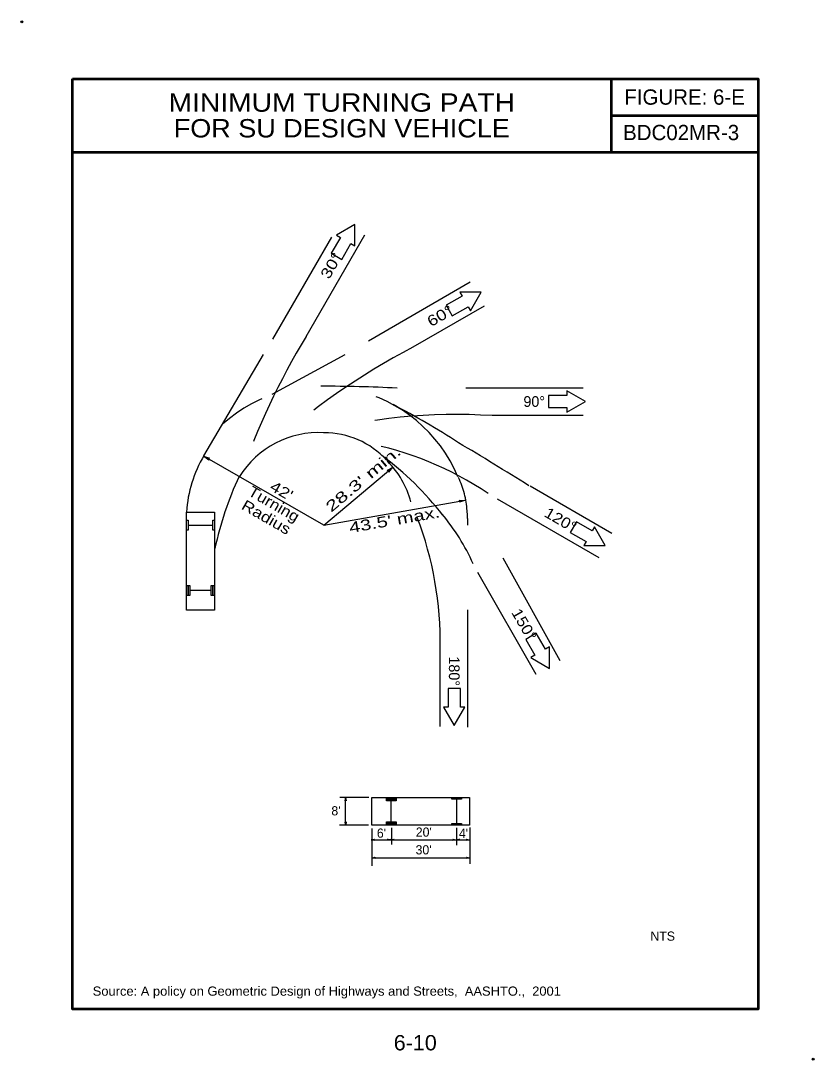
# Model space of a CAD drawing. Extents: x -3.355 to -2.68, y 3.973 to 4.857.
import ezdxf
from ezdxf.enums import TextEntityAlignment as Align

# ---------------------------------------------------------------- set-up
doc = ezdxf.new("R2010")
doc.units = 0
doc.header["$LTSCALE"] = 0.0036
doc.header["$PDMODE"] = 32
doc.header["$PDSIZE"] = 0.0018
doc.linetypes.add('LONG_DASHED', pattern=[7.5, 6, -1.5])
for name, color, linetype, lineweight in [('1', 7, 'Continuous', 25), ('2', 7, 'LONG_DASHED', 25), ('3', 7, 'Continuous', 25)]:
    doc.layers.add(name, color=color, linetype=linetype, lineweight=lineweight)

msp = doc.modelspace()

# ---------------------------------------------------------------- linework, layer by layer
at = {"layer": '1', "lineweight": 53}
for p, q in [((-2.852792, 4.80765), (-2.852792, 4.74515)), ((-2.852792, 4.7764), (-2.727792, 4.7764)), ((-3.311125, 4.74515), (-2.727792, 4.74515))]:
    msp.add_line(p, q, dxfattribs=at)
at = {"layer": '1', "linetype": 'LONG_DASHED'}
for p, q in [((-3.140583, 4.586158), (-3.081925, 4.687733)), ((-3.11225, 4.588325), (-3.0616, 4.67605)), ((-2.972667, 4.634425), (-3.078375, 4.573392)), ((-2.96095, 4.614117), (-3.021475, 4.579175)), ((-3.1993, 4.4869), (-3.140708, 4.586158)), ((-3.141308, 4.539217), (-3.079075, 4.573025)), ((-2.876517, 4.544392), (-3.034783, 4.544392)), ((-2.876517, 4.52095), (-2.954033, 4.52095)), ((-2.896075, 4.31235), (-2.983125, 4.469017)), ((-2.852075, 4.4208), (-2.921683, 4.460992)), ((-2.862925, 4.399992), (-2.957467, 4.4546)), ((-2.916583, 4.3007), (-2.970717, 4.395533))]:
    msp.add_line(p, q, dxfattribs=at)
at = {"layer": '1'}
for p, q in [((-3.199583, 4.486483), (-3.194467, 4.484717)), ((-3.038725, 4.477025), (-3.042342, 4.473008)), ((-2.976633, 4.448975), (-2.981783, 4.447308)), ((-3.212592, 4.427767), (-3.191758, 4.427767)), ((-3.193142, 4.3722), (-3.2112, 4.3722)), ((-3.05905, 4.196133), (-3.083533, 4.196133)), ((-3.078683, 4.17245), (-3.078683, 4.196175)), ((-3.078675, 4.196033), (-3.078283, 4.193358)), ((-3.039867, 4.175283), (-3.039867, 4.193342)), ((-2.9843, 4.194733), (-2.9843, 4.1739)), ((-3.078658, 4.172525), (-3.07905, 4.1752)), ((-3.059267, 4.172517), (-3.084033, 4.172517)), ((-3.056542, 4.169742), (-3.056542, 4.137975)), ((-3.03975, 4.170383), (-3.03975, 4.155983)), ((-2.984225, 4.170158), (-2.984225, 4.15555)), ((-2.973, 4.170492), (-2.973, 4.139617)), ((-3.056925, 4.160208), (-2.973517, 4.160208)), ((-3.05685, 4.160175), (-3.054175, 4.160575)), ((-3.04025, 4.160242), (-3.042925, 4.159842)), ((-3.040025, 4.160225), (-3.03735, 4.160625)), ((-2.984675, 4.160183), (-2.98735, 4.159792)), ((-2.984592, 4.160225), (-2.981917, 4.160625)), ((-2.973383, 4.160217), (-2.976058, 4.159825)), ((-3.05645, 4.1449), (-3.053767, 4.1453)), ((-3.056433, 4.1449), (-2.973, 4.1449)), ((-2.973033, 4.144908), (-2.975708, 4.144517))]:
    msp.add_line(p, q, dxfattribs=at)
at = {"layer": '1', "lineweight": 53}
msp.add_lwpolyline([(-3.311125, 4.80765), (-2.727792, 4.80765), (-2.727792, 4.015983), (-3.311125, 4.015983)], close=True, dxfattribs=at)
at = {"layer": '1'}
for points in [[(-3.090975, 4.659092), (-3.081958, 4.653883), (-3.074142, 4.667408), (-3.070767, 4.66545), (-3.070758, 4.683692), (-3.086558, 4.674575), (-3.083167, 4.672617)], [(-2.993217, 4.614867), (-2.988008, 4.60585), (-2.974475, 4.613658), (-2.972533, 4.610275), (-2.963408, 4.626067), (-2.981642, 4.626067), (-2.979683, 4.622683)], [(-2.905975, 4.538192), (-2.905975, 4.527775), (-2.89035, 4.527775), (-2.89035, 4.523867), (-2.874558, 4.532983), (-2.89035, 4.5421), (-2.89035, 4.538192)], [(-3.190375, 4.438867), (-3.190375, 4.355533), (-3.213992, 4.355533), (-3.213992, 4.438867)], [(-3.213992, 4.4236), (-3.213992, 4.431933), (-3.212592, 4.431933), (-3.212592, 4.4236)], [(-3.191758, 4.4236), (-3.191758, 4.431933), (-3.190367, 4.431933), (-3.190367, 4.4236)], [(-2.882392, 4.430658), (-2.8876, 4.421642), (-2.874075, 4.413825), (-2.876033, 4.41045), (-2.857792, 4.410442), (-2.866908, 4.426242), (-2.868867, 4.42285)], [(-3.213992, 4.368033), (-3.213992, 4.376367), (-3.212592, 4.376367), (-3.212592, 4.368033)], [(-3.212592, 4.368033), (-3.212592, 4.376367), (-3.2112, 4.376367), (-3.2112, 4.368033)], [(-3.193142, 4.368033), (-3.193142, 4.376367), (-3.19175, 4.376367), (-3.19175, 4.368033)], [(-3.19175, 4.368033), (-3.19175, 4.376367), (-3.19035, 4.376367), (-3.19035, 4.368033)], [(-2.916458, 4.3358), (-2.925475, 4.330592), (-2.917667, 4.317058), (-2.92105, 4.315108), (-2.905258, 4.305983), (-2.905258, 4.324225), (-2.908642, 4.322267)], [(-2.98105, 4.288692), (-2.991467, 4.288692), (-2.991467, 4.273067), (-2.995375, 4.273067), (-2.986258, 4.257275), (-2.977142, 4.273067), (-2.98105, 4.273067)], [(-2.9732, 4.172517), (-3.056533, 4.172517), (-3.056533, 4.196133), (-2.9732, 4.196133)], [(-3.044033, 4.196133), (-3.0357, 4.196133), (-3.0357, 4.194733), (-3.044033, 4.194733)], [(-3.044033, 4.194733), (-3.0357, 4.194733), (-3.0357, 4.193342), (-3.044033, 4.193342)], [(-2.988467, 4.196133), (-2.980133, 4.196133), (-2.980133, 4.194733), (-2.988467, 4.194733)], [(-3.044033, 4.175283), (-3.0357, 4.175283), (-3.0357, 4.173892), (-3.044033, 4.173892)], [(-2.988467, 4.1739), (-2.980133, 4.1739), (-2.980133, 4.172508), (-2.988467, 4.172508)], [(-3.044033, 4.173892), (-3.0357, 4.173892), (-3.0357, 4.172492), (-3.044033, 4.172492)]]:
    msp.add_lwpolyline(points, close=True, dxfattribs=at)
for points in [[(-3.195633, 4.484442), (-3.195117, 4.483192), (-3.199633, 4.486525)], [(-3.194467, 4.484692), (-3.195625, 4.484467), (-3.195633, 4.484442)], [(-3.042142, 4.474183), (-3.0435, 4.474183), (-3.038675, 4.477067)], [(-3.042367, 4.473008), (-3.042125, 4.474158), (-3.042142, 4.474183)], [(-2.981017, 4.448225), (-2.982183, 4.4489), (-2.976575, 4.448975)], [(-2.9818, 4.447325), (-2.981008, 4.4482), (-2.981017, 4.448225)], [(-3.078667, 4.193808), (-3.0791, 4.193283), (-3.078667, 4.196067)], [(-3.078292, 4.19335), (-3.078658, 4.193808), (-3.078667, 4.193808)], [(-3.079042, 4.175217), (-3.078667, 4.174758), (-3.078658, 4.174758)], [(-3.078658, 4.174758), (-3.078225, 4.175275), (-3.078658, 4.172492)], [(-3.054625, 4.160175), (-3.0541, 4.15975), (-3.056883, 4.160175)], [(-3.054167, 4.160558), (-3.054625, 4.160183), (-3.054625, 4.160175)], [(-3.042475, 4.160242), (-3.043, 4.160667), (-3.040217, 4.160242)], [(-3.042933, 4.15985), (-3.042475, 4.160225), (-3.042475, 4.160242)], [(-3.0378, 4.160225), (-3.037275, 4.1598), (-3.040058, 4.160225)], [(-3.037342, 4.160617), (-3.0378, 4.160242), (-3.0378, 4.160225)], [(-2.9869, 4.160183), (-2.987425, 4.160617), (-2.984642, 4.160183)], [(-2.987358, 4.1598), (-2.9869, 4.160175), (-2.9869, 4.160183)], [(-2.982358, 4.160225), (-2.981842, 4.1598), (-2.984625, 4.160225)], [(-2.9819, 4.160617), (-2.982358, 4.160242), (-2.982358, 4.160225)], [(-2.975608, 4.160217), (-2.976133, 4.160642), (-2.97335, 4.160217)], [(-2.976067, 4.159833), (-2.975608, 4.160208), (-2.975608, 4.160217)], [(-3.054217, 4.1449), (-3.0537, 4.144475), (-3.056475, 4.1449)], [(-3.053758, 4.145283), (-3.054217, 4.144908), (-3.054217, 4.1449)], [(-2.975258, 4.144908), (-2.975783, 4.145342), (-2.973, 4.144908)], [(-2.975717, 4.144525), (-2.975258, 4.1449), (-2.975258, 4.144908)]]:
    msp.add_lwpolyline(points, dxfattribs=at)
at = {"layer": '1', "linetype": 'LONG_DASHED'}
for centre, radius, start, end in [((-2.581853, 4.265445), 0.620945, 148.6687, 160.86742), ((-2.745364, 4.049847), 0.597011, 117.54806, 132.13997), ((-3.099227, 4.419944), 0.126048, 22.9111, 131.90028), ((-3.104354, 3.078547), 1.467486, 87.28863, 89.81771), ((-3.367637, 3.899842), 0.711285, 57.23241, 62.42469), ((-2.984756, 4.049399), 0.472553, 86.27182, 105.25757), ((-3.101787, 4.427354), 0.079167, 86.83392, 148.18627), ((-3.096638, 4.435152), 0.07125, 42.27058, 90.42364), ((-3.113325, 4.225211), 0.277326, 55.80558, 79.54229), ((-4.71149, 1.593066), 3.380396, 58.0504, 59.24109), ((-3.105582, 4.431541), 0.108847, 149.42985, 176.08488), ((-3.212844, 4.267082), 0.275031, 37.97045, 53.11266), ((-3.097352, 4.427723), 0.076827, 15.00097, 45.11046), ((-2.919766, 4.350889), 0.276122, 154.65514, 168.0712), ((-3.055659, 4.434777), 0.080468, 3.73943, 24.74749), ((-3.294494, 4.328787), 0.296225, 1.66405, 23.648), ((-3.097113, 4.42766), 0.122396, 0, 5.73308), ((-3.130211, 4.324531), 0.174751, 23.72372, 40.15246)]:
    msp.add_arc(centre, radius, start, end, dxfattribs=at)
at = {"layer": '1'}
for p in [(-3.354217, 4.855992), (-2.680883, 3.973492)]:
    msp.add_point(p, dxfattribs=at)
at = {"layer": '2', "linetype": 'Continuous'}
msp.add_line((-3.09735, 4.427725), (-3.198383, 4.486058), dxfattribs=at)
at = {"layer": '2'}
for p, q in [((-2.974658, 4.255825), (-2.974658, 4.427533)), ((-2.998392, 4.256508), (-2.998392, 4.337392))]:
    msp.add_line(p, q, dxfattribs=at)
at = {"layer": '3'}
for q in [(-3.0385, 4.477108), (-2.976825, 4.448975)]:
    msp.add_line((-3.09735, 4.427725), q, dxfattribs=at)

# ---------------------------------------------------------------- texts
at = {"layer": '1'}
for s, height, width, p in [('MINIMUM TURNING PATH', 0.01562, 1.15, (-3.081958, 4.779525)), ('FOR SU DESIGN VEHICLE', 0.01562, 1.1, (-3.081962, 4.75765)), ('6-10', 0.01303, 1.05, (-3.019458, 3.980958))]:
    msp.add_text(s, height=height, dxfattribs=dict(at, width=width)).set_placement(p, align=Align.CENTER)
for s, height, p in [('FIGURE: 6-E', 0.01303, (-2.790296, 4.785508)), ('BDC02MR-3', 0.01303, (-2.793238, 4.755333)), ("8'", 0.007817, (-3.086929, 4.180867)), ("6'", 0.007817, (-3.048208, 4.161892)), ("20'", 0.007817, (-3.012192, 4.16275)), ("4'", 0.007817, (-2.9784, 4.161708)), ("30'", 0.007817, (-3.012375, 4.147675)), ('NTS', 0.007817, (-2.808912, 4.07425))]:
    msp.add_text(s, height=height, dxfattribs=at).set_placement(p, align=Align.CENTER)
for s, rotation, width, p in [('30°', 60, 1.25, (-3.081288, 4.656337)), ('60°', 30, 1.25, (-2.986079, 4.607716)), ('120°', 330, 1.15, (-2.885454, 4.421147)), ('150°', 300, 1.15, (-2.923497, 4.328454))]:
    msp.add_text(s, height=0.009108, rotation=rotation, dxfattribs=dict(at, width=width)).set_placement(p, align=Align.RIGHT)
msp.add_text('90°', height=0.009108, dxfattribs=at).set_placement((-2.909, 4.528425), align=Align.RIGHT)
for s, rotation, width, p in [("28.3' min.", 40.001, 1.5, (-3.060851, 4.463596)), ('Turning', 329.999, 1.15, (-3.141963, 4.441873)), ("42'", 329.999, 1.25, (-3.13545, 4.453163)), ('Radius', 329.999, 1.2, (-3.148479, 4.430595)), ("43.5' max.", 9.999, 1.4, (-3.036391, 4.427815))]:
    msp.add_text(s, height=0.009117, rotation=rotation, dxfattribs=dict(at, width=width)).set_placement(p, align=Align.CENTER)
msp.add_text('180°', height=0.009108, rotation=270, dxfattribs=at).set_placement((-2.990817, 4.290917), align=Align.RIGHT)
at = {"layer": '1', "width": 1.05}
msp.add_text('Source: A policy on Geometric Design of Highways and Streets,  AASHTO.,  2001', height=0.007817, dxfattribs=at).set_placement((-3.2939, 4.027467))

doc.saveas('drawing.dxf')
